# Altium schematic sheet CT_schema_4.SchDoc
size 282 x 169 mm
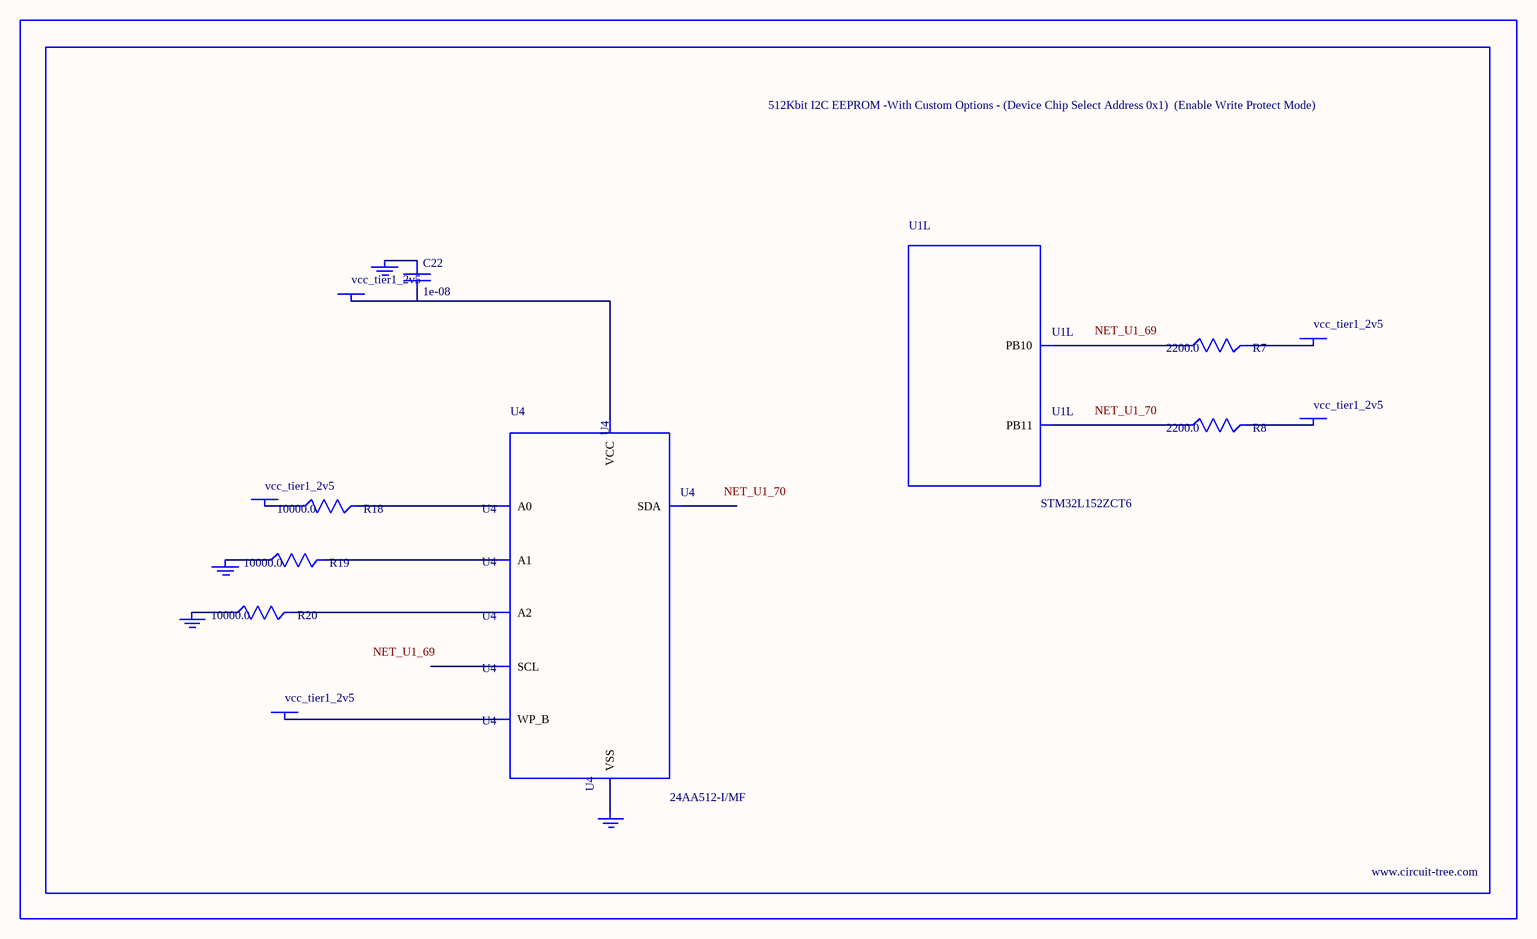
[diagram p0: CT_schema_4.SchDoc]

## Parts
BORDER3  (no value)
C22  1e-08  [C0402]
GND_INSTANCE_3_0  (no value)
GND_INSTANCE_3_1  (no value)
GND_INSTANCE_3_2  (no value)
GND_INSTANCE_3_3  (no value)
POWER_INSTANCE_3_0  vcc_tier1_2v5
POWER_INSTANCE_3_1  vcc_tier1_2v5
POWER_INSTANCE_3_2  vcc_tier1_2v5
POWER_INSTANCE_3_3  vcc_tier1_2v5
POWER_INSTANCE_3_4  vcc_tier1_2v5
R7  2200.0  [R0603]
R8  2200.0  [R0603]
R18  10000.0  [R0603]
R19  10000.0  [R0603]
R20  10000.0  [R0603]
U1  STM32L152ZCT6  [LQFP144]  (part L of 13)
U4  24AA512-I/MF  [DFN8-S]

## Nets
NetC22_1: C22.1 GND_INSTANCE_3_2.0(GND)
NetC22_2: C22.2 POWER_INSTANCE_3_2.0(PWR) U4.8(VCC)
NetGND_INSTANCE_3_0_0: GND_INSTANCE_3_0.0(GND) R19.1
NetGND_INSTANCE_3_1_0: GND_INSTANCE_3_1.0(GND) R20.1
NetGND_INSTANCE_3_3_0: GND_INSTANCE_3_3.0(GND) U4.4(VSS)
NetPOWER_INSTANCE_3_0_0: POWER_INSTANCE_3_0.0(PWR) R18.1
NetPOWER_INSTANCE_3_1_0: POWER_INSTANCE_3_1.0(PWR) U4.7(WP_B)
NetPOWER_INSTANCE_3_3_0: POWER_INSTANCE_3_3.0(PWR) R7.2
NetPOWER_INSTANCE_3_4_0: POWER_INSTANCE_3_4.0(PWR) R8.2
NetR7_1: R7.1 U1.69(PB10)
NetR8_1: R8.1 U1.70(PB11)
NetR18_2: R18.2 U4.1(A0)
NetR19_2: R19.2 U4.2(A1)
NetR20_2: R20.2 U4.3(A2)

Not connected (* = marked no-connect by the designer): U4 5(SDA) 6(SCL)

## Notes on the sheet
- Labels drawn without touching a wire or pin: NET_U1_69, NET_U1_70

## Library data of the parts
BORDER3 = BORDER_PAGE3
C22 = C0402C103K3RAC
GND_INSTANCE_3_0-GND_INSTANCE_3_3 = GND
POWER_INSTANCE_3_0-POWER_INSTANCE_3_4 = PWR
R7 R8 = RC0603JR-072K2L
R18-R20 = RC0603JR-0710KL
